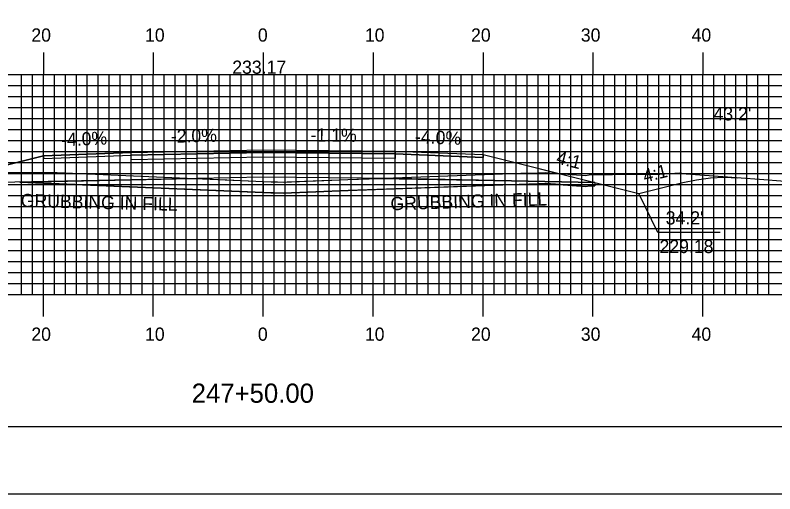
# Model space of a CAD drawing. Extents: x 1803503 to 1803847, y 442591 to 442811.
# Drawn here: x 1803646.6 to 1803715.7, y 442590.5 to 442634.1 of the extents above; entities that cross this region are included whole.
import ezdxf

# ---------------------------------------------------------------- set-up
doc = ezdxf.new("R2010")
doc.units = 0
for name, color, linetype in [('ANNOTATION', 7, 'Continuous'), ('BORDER', 7, 'Continuous'), ('D_Roadway_Centerline', 7, 'Continuous'), ('D_Roadway_Centerline_Text', 7, 'Continuous'), ('D_Roadway_Edge_Shoulder', 7, 'Continuous'), ('D_Roadway_Edge_TW', 7, 'Continuous'), ('D_Roadway_Pavement', 7, 'Continuous'), ('D_Roadway_SlopeLines', 7, 'Continuous'), ('D_Roadway_SubGrade', 7, 'Continuous'), ('D_Text_Standard', 7, 'Continuous'), ('GRUBBING IN FILL', 7, 'Continuous'), ('H_V ANNOTATION', 7, 'Continuous'), ('MAJOR', 7, 'Continuous'), ('MINOR', 7, 'Continuous'), ('PLOT BOUNDARY', 7, 'Continuous'), ('S_Roadway_Centerline', 7, 'Continuous')]:
    doc.layers.add(name, color=color, linetype=linetype)

msp = doc.modelspace()

# ---------------------------------------------------------------- linework, layer by layer
at = {"layer": 'ANNOTATION'}
msp.add_lwpolyline([(1803710.719, 442614.311), (1803705.028, 442614.311), (1803703.315, 442617.846)], dxfattribs=at)
at = {"layer": 'BORDER'}
msp.add_lwpolyline([(1803519.541, 442596.665), (1803839.541, 442596.665), (1803839.541, 442806.665), (1803519.541, 442806.665)], close=True, dxfattribs=at)
at = {"layer": 'D_Roadway_Centerline'}
msp.add_lwpolyline([(1803623.31, 442620.005), (1803624.56, 442619.974), (1803625.81, 442619.862), (1803627.06, 442619.67), (1803628.31, 442619.398), (1803634.967, 442617.734), (1803638.967, 442618.734), (1803649.141, 442621.278), (1803657.141, 442621.598), (1803669.141, 442621.838), (1803681.141, 442621.71), (1803689.141, 442621.39), (1803699.315, 442618.846), (1803703.315, 442617.846), (1803707.321, 442618.848), (1803708.571, 442619.11), (1803709.821, 442619.272), (1803711.071, 442619.333), (1803712.321, 442619.293)], dxfattribs=at)
at = {"layer": 'D_Roadway_Edge_Shoulder'}
for points in [[(1803657.141, 442621.598), (1803649.141, 442621.278), (1803649.141, 442621.028), (1803657.141, 442621.348)], [(1803681.141, 442621.71), (1803689.141, 442621.39), (1803689.141, 442621.14), (1803681.141, 442621.46)]]:
    msp.add_lwpolyline(points, close=True, dxfattribs=at)
at = {"layer": 'D_Roadway_Edge_TW'}
msp.add_lwpolyline([(1803657.141, 442621.348), (1803657.141, 442621.598), (1803669.141, 442621.838), (1803681.141, 442621.71), (1803681.141, 442621.46), (1803669.141, 442621.588)], close=True, dxfattribs=at)
at = {"layer": 'D_Roadway_Pavement'}
msp.add_lwpolyline([(1803657.141, 442620.931), (1803657.141, 442621.348), (1803669.141, 442621.588), (1803681.141, 442621.46), (1803681.141, 442621.043), (1803669.141, 442621.171)], close=True, dxfattribs=at)
at = {"layer": 'D_Roadway_SlopeLines'}
for points in [[(1803649.141, 442621.278), (1803634.967, 442617.734)], [(1803689.141, 442621.39), (1803703.315, 442617.846)], [(1803703.315, 442617.846), (1803707.321, 442618.848), (1803708.571, 442619.11), (1803709.821, 442619.272), (1803711.071, 442619.333), (1803712.321, 442619.293)]]:
    msp.add_lwpolyline(points, dxfattribs=at)
at = {"layer": 'D_Roadway_SubGrade'}
msp.add_lwpolyline([(1803657.141, 442619.097), (1803638.967, 442618.734), (1803649.141, 442621.278), (1803649.141, 442621.028), (1803657.141, 442621.348), (1803669.141, 442621.588), (1803681.141, 442621.46), (1803689.141, 442621.14), (1803689.141, 442621.39), (1803699.315, 442618.846), (1803681.141, 442619.21), (1803669.141, 442619.337)], close=True, dxfattribs=at)
at = {"layer": 'GRUBBING IN FILL'}
for p, q in [((1803669.141, 442618.954), (1803669.141, 442617.954)), ((1803669.141, 442617.954), (1803669.141, 442618.954)), ((1803669.141, 442618.954), (1803669.141, 442617.954)), ((1803669.141, 442617.954), (1803669.141, 442618.954)), ((1803699.315, 442618.846), (1803699.315, 442618.547)), ((1803699.315, 442618.846), (1803699.315, 442618.547))]:
    msp.add_line(p, q, dxfattribs=at)
for points in [[(1803669.141, 442617.954), (1803658.425, 442618.41), (1803647.016, 442618.895), (1803657.141, 442619.097), (1803662.596, 442619.207), (1803663.017, 442619.215), (1803663.818, 442619.181), (1803669.141, 442618.954)], [(1803669.141, 442617.954), (1803658.425, 442618.41), (1803647.016, 442618.895), (1803657.141, 442619.097), (1803662.596, 442619.207), (1803663.017, 442619.215), (1803663.818, 442619.181), (1803669.141, 442618.954)], [(1803647.016, 442618.895), (1803669.834, 442617.924), (1803671, 442617.896), (1803676.884, 442618.12), (1803692.595, 442618.693), (1803694.167, 442618.723), (1803694.813, 442618.761), (1803698.47, 442618.503), (1803698.856, 442618.54), (1803699.315, 442618.547)], [(1803647.016, 442618.895), (1803669.834, 442617.924), (1803671, 442617.896), (1803676.884, 442618.12), (1803692.595, 442618.693), (1803694.167, 442618.723), (1803694.813, 442618.761), (1803698.47, 442618.503), (1803698.856, 442618.54), (1803699.315, 442618.547)], [(1803669.141, 442618.954), (1803669.868, 442618.924), (1803670.43, 442618.91), (1803670.993, 442618.896), (1803671.321, 442618.909), (1803676.847, 442619.119), (1803679.748, 442619.225), (1803690.228, 442619.028), (1803699.315, 442618.846), (1803699.315, 442618.547), (1803699.086, 442618.543), (1803698.856, 442618.54), (1803698.663, 442618.521), (1803698.47, 442618.503), (1803696.641, 442618.632), (1803694.813, 442618.761), (1803694.49, 442618.742), (1803694.167, 442618.723), (1803684.74, 442618.406), (1803676.884, 442618.12), (1803671, 442617.896), (1803669.141, 442617.954)], [(1803669.141, 442618.954), (1803669.868, 442618.924), (1803670.43, 442618.91), (1803670.993, 442618.896), (1803671.321, 442618.909), (1803676.847, 442619.119), (1803679.748, 442619.225), (1803690.228, 442619.028), (1803699.315, 442618.846), (1803699.315, 442618.547), (1803699.086, 442618.543), (1803698.856, 442618.54), (1803698.663, 442618.521), (1803698.47, 442618.503), (1803696.641, 442618.632), (1803694.813, 442618.761), (1803694.49, 442618.742), (1803694.167, 442618.723), (1803684.74, 442618.406), (1803676.884, 442618.12), (1803671, 442617.896), (1803669.141, 442617.954)]]:
    msp.add_lwpolyline(points, dxfattribs=at)
at = {"layer": 'MAJOR'}
for p, q in [((1803649.141, 442630.669), (1803649.141, 442628.665)), ((1803659.141, 442630.669), (1803659.141, 442628.665)), ((1803669.141, 442630.669), (1803669.141, 442628.665)), ((1803679.141, 442630.669), (1803679.141, 442628.665)), ((1803689.141, 442630.669), (1803689.141, 442628.665)), ((1803699.141, 442630.669), (1803699.141, 442628.665)), ((1803709.141, 442630.669), (1803709.141, 442628.665)), ((1803529.141, 442628.665), (1803809.141, 442628.665)), ((1803529.141, 442628.665), (1803809.141, 442628.665)), ((1803649.141, 442608.665), (1803649.141, 442628.665)), ((1803659.141, 442608.665), (1803659.141, 442628.665)), ((1803669.141, 442608.665), (1803669.141, 442628.665)), ((1803679.141, 442608.665), (1803679.141, 442628.665)), ((1803689.141, 442608.665), (1803689.141, 442628.665)), ((1803699.141, 442608.665), (1803699.141, 442628.665)), ((1803709.141, 442608.665), (1803709.141, 442628.665)), ((1803529.141, 442623.665), (1803809.141, 442623.665)), ((1803529.141, 442618.665), (1803809.141, 442618.665)), ((1803529.141, 442613.665), (1803809.141, 442613.665)), ((1803529.141, 442608.665), (1803809.141, 442608.665)), ((1803529.141, 442608.665), (1803809.141, 442608.665)), ((1803649.141, 442606.661), (1803649.141, 442608.665)), ((1803659.141, 442606.661), (1803659.141, 442608.665)), ((1803669.141, 442606.661), (1803669.141, 442608.665)), ((1803679.141, 442606.661), (1803679.141, 442608.665)), ((1803689.141, 442606.661), (1803689.141, 442608.665)), ((1803699.141, 442606.661), (1803699.141, 442608.665)), ((1803709.141, 442606.661), (1803709.141, 442608.665))]:
    msp.add_line(p, q, dxfattribs=at)
at = {"layer": 'MINOR'}
for p, q in [((1803647.141, 442608.665), (1803647.141, 442628.665)), ((1803648.141, 442608.665), (1803648.141, 442628.665)), ((1803650.141, 442608.665), (1803650.141, 442628.665)), ((1803651.141, 442608.665), (1803651.141, 442628.665)), ((1803652.141, 442608.665), (1803652.141, 442628.665)), ((1803653.141, 442608.665), (1803653.141, 442628.665)), ((1803654.141, 442608.665), (1803654.141, 442628.665)), ((1803655.141, 442608.665), (1803655.141, 442628.665)), ((1803656.141, 442608.665), (1803656.141, 442628.665)), ((1803657.141, 442608.665), (1803657.141, 442628.665)), ((1803658.141, 442608.665), (1803658.141, 442628.665)), ((1803660.141, 442608.665), (1803660.141, 442628.665)), ((1803661.141, 442608.665), (1803661.141, 442628.665)), ((1803662.141, 442608.665), (1803662.141, 442628.665)), ((1803663.141, 442608.665), (1803663.141, 442628.665)), ((1803664.141, 442608.665), (1803664.141, 442628.665)), ((1803665.141, 442608.665), (1803665.141, 442628.665)), ((1803666.141, 442608.665), (1803666.141, 442628.665)), ((1803667.141, 442608.665), (1803667.141, 442628.665)), ((1803668.141, 442608.665), (1803668.141, 442628.665)), ((1803670.141, 442608.665), (1803670.141, 442628.665)), ((1803671.141, 442608.665), (1803671.141, 442628.665)), ((1803672.141, 442608.665), (1803672.141, 442628.665)), ((1803673.141, 442608.665), (1803673.141, 442628.665)), ((1803674.141, 442608.665), (1803674.141, 442628.665)), ((1803675.141, 442608.665), (1803675.141, 442628.665)), ((1803676.141, 442608.665), (1803676.141, 442628.665)), ((1803677.141, 442608.665), (1803677.141, 442628.665)), ((1803678.141, 442608.665), (1803678.141, 442628.665)), ((1803680.141, 442608.665), (1803680.141, 442628.665)), ((1803681.141, 442608.665), (1803681.141, 442628.665)), ((1803682.141, 442608.665), (1803682.141, 442628.665)), ((1803683.141, 442608.665), (1803683.141, 442628.665)), ((1803684.141, 442608.665), (1803684.141, 442628.665)), ((1803685.141, 442608.665), (1803685.141, 442628.665)), ((1803686.141, 442608.665), (1803686.141, 442628.665)), ((1803687.141, 442608.665), (1803687.141, 442628.665)), ((1803688.141, 442608.665), (1803688.141, 442628.665)), ((1803690.141, 442608.665), (1803690.141, 442628.665)), ((1803691.141, 442608.665), (1803691.141, 442628.665)), ((1803692.141, 442608.665), (1803692.141, 442628.665)), ((1803693.141, 442608.665), (1803693.141, 442628.665)), ((1803694.141, 442608.665), (1803694.141, 442628.665)), ((1803695.141, 442608.665), (1803695.141, 442628.665)), ((1803696.141, 442608.665), (1803696.141, 442628.665)), ((1803697.141, 442608.665), (1803697.141, 442628.665)), ((1803698.141, 442608.665), (1803698.141, 442628.665)), ((1803700.141, 442608.665), (1803700.141, 442628.665)), ((1803701.141, 442608.665), (1803701.141, 442628.665)), ((1803702.141, 442608.665), (1803702.141, 442628.665)), ((1803703.141, 442608.665), (1803703.141, 442628.665)), ((1803704.141, 442608.665), (1803704.141, 442628.665)), ((1803705.141, 442608.665), (1803705.141, 442628.665)), ((1803706.141, 442608.665), (1803706.141, 442628.665)), ((1803707.141, 442608.665), (1803707.141, 442628.665)), ((1803708.141, 442608.665), (1803708.141, 442628.665)), ((1803710.141, 442608.665), (1803710.141, 442628.665)), ((1803711.141, 442608.665), (1803711.141, 442628.665)), ((1803712.141, 442608.665), (1803712.141, 442628.665)), ((1803713.141, 442608.665), (1803713.141, 442628.665)), ((1803714.141, 442608.665), (1803714.141, 442628.665)), ((1803715.141, 442608.665), (1803715.141, 442628.665)), ((1803529.141, 442627.665), (1803809.141, 442627.665)), ((1803529.141, 442626.665), (1803809.141, 442626.665)), ((1803529.141, 442625.665), (1803809.141, 442625.665)), ((1803529.141, 442624.665), (1803809.141, 442624.665)), ((1803529.141, 442622.665), (1803809.141, 442622.665)), ((1803529.141, 442621.665), (1803809.141, 442621.665)), ((1803529.141, 442620.665), (1803809.141, 442620.665)), ((1803529.141, 442619.665), (1803809.141, 442619.665)), ((1803529.141, 442617.665), (1803809.141, 442617.665)), ((1803529.141, 442616.665), (1803809.141, 442616.665)), ((1803529.141, 442615.665), (1803809.141, 442615.665)), ((1803529.141, 442614.665), (1803809.141, 442614.665)), ((1803529.141, 442612.665), (1803809.141, 442612.665)), ((1803529.141, 442611.665), (1803809.141, 442611.665)), ((1803529.141, 442610.665), (1803809.141, 442610.665)), ((1803529.141, 442609.665), (1803809.141, 442609.665))]:
    msp.add_line(p, q, dxfattribs=at)
at = {"layer": 'PLOT BOUNDARY'}
msp.add_lwpolyline([(1803503.354, 442590.547), (1803843.354, 442590.547), (1803843.354, 442810.547), (1803503.354, 442810.547)], close=True, dxfattribs=at)
at = {"layer": 'S_Roadway_Centerline'}
msp.add_lwpolyline([(1803606.544, 442619.896), (1803611.858, 442619.837), (1803617.407, 442619.986), (1803624.006, 442620.007), (1803628.692, 442620.049), (1803635.445, 442619.815), (1803643.711, 442619.794), (1803647.236, 442619.774), (1803650.385, 442619.753), (1803669.868, 442618.924), (1803670.993, 442618.896), (1803676.847, 442619.119), (1803692.567, 442619.692), (1803694.128, 442619.723), (1803694.819, 442619.763), (1803698.458, 442619.507), (1803698.802, 442619.539), (1803703.061, 442619.604), (1803705.219, 442619.608), (1803707.043, 442619.737), (1803707.607, 442619.632), (1803714.277, 442619.152), (1803721.289, 442618.626)], dxfattribs=at)

# ---------------------------------------------------------------- texts
at = {"layer": 'ANNOTATION'}
for s, rotation, p in [('-2.0%', 1.14576, (1803660.747, 442622.47)), ('-1.1%', 359.39111, (1803673.451, 442622.592)), ('-4.0%', 2.29061, (1803650.773, 442622.144)), ('-4.0%', 357.70939, (1803682.933, 442622.44)), ('4:1', 345.96376, (1803695.734, 442620.603)), ('4:1', 14.03624, (1803703.854, 442618.843))]:
    msp.add_text(s, height=1.2, rotation=rotation, dxfattribs=at).set_placement(p)
for s, p in [("34.2'", (1803705.762, 442615.037)), ('229.18', (1803705.195, 442612.437))]:
    msp.add_text(s, height=1.2, dxfattribs=at).set_placement(p)
at = {"layer": 'D_Roadway_Centerline'}
for s, p in [('C', (1803669.136, 442621.838)), ('L', (1803669.141, 442621.83))]:
    msp.add_text(s, height=0.0146, dxfattribs=at).set_placement(p)
at = {"layer": 'D_Roadway_Centerline_Text'}
msp.add_text('233.17', height=1.2, dxfattribs=at).set_placement((1803666.326, 442628.742))
at = {"layer": 'D_Text_Standard'}
msp.add_text("43.2'", height=1.2, dxfattribs=at).set_placement((1803710.111, 442624.499))
at = {"layer": 'GRUBBING IN FILL'}
for rotation, p in [(358.55884, (1803647.073, 442616.633)), (1.78347, (1803680.737, 442616.326))]:
    msp.add_text('GRUBBING IN FILL', height=1.2, rotation=rotation, dxfattribs=at).set_placement(p)
at = {"layer": 'H_V ANNOTATION'}
for s, height, p in [('20', 1.2, (1803648.049, 442631.665)), ('10', 1.2, (1803658.392, 442631.665)), ('0', 1.2, (1803668.659, 442631.665)), ('10', 1.2, (1803678.392, 442631.665)), ('20', 1.2, (1803688.049, 442631.665)), ('30', 1.2, (1803698.038, 442631.665)), ('40', 1.2, (1803708.113, 442631.665)), ('20', 1.2, (1803648.049, 442604.465)), ('10', 1.2, (1803658.392, 442604.465)), ('0', 1.2, (1803668.659, 442604.465)), ('10', 1.2, (1803678.392, 442604.465)), ('20', 1.2, (1803688.049, 442604.465)), ('30', 1.2, (1803698.038, 442604.465)), ('40', 1.2, (1803708.113, 442604.465)), ('247+50.00', 1.75, (1803662.633, 442598.821))]:
    msp.add_text(s, height=height, dxfattribs=at).set_placement(p)

doc.saveas('drawing.dxf')
